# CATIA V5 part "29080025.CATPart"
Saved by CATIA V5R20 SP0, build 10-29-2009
Part number: 29080025
Definition: NONE
Nomenclature: 29080025
Source: Unknown
Description: 29080025
Bounding box of the stored display mesh (mm): x -12.5 to 44.548, y -54 to 88.548, z -44 to 44
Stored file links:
  C:\Users\Utente\Desktop\IO LAVORO\3D X SITO CF\X SITO\PLASTICA\RF1\29080025.CATPart
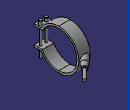
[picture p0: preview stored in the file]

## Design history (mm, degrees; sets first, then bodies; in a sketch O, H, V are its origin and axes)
Body1 "29080025" (main body)
  Solid1: solid without history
